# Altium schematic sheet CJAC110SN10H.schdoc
size 127 x 101 mm
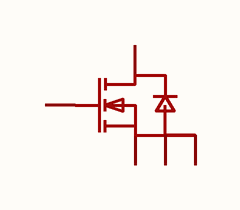
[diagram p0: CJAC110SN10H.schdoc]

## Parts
Q?  cjac110sn10h  [TDSON-8_L5.9-W5.2-P1.27-BL]  (value not drawn)

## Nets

Not connected (* = marked no-connect by the designer): Q? 1(S) 2(S) 3(S) 4(G) 5(D)

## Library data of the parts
Q? = cjac110sn10h: 数量:1个N沟道;漏源电压(Vdss):100V;连续漏极电流(Id):110A;导通电阻(RDS(on)):5.2mΩ@10V;耗散功率(Pd):130W;阈值电压(Vgs(th)):4V;; Manufacturer: CJ(江苏长电/长晶); AddInBom: yes; ModelId: ff3d8edf19694f3eb1c5df98919f3bc8; ModelTransform: 216.9287,242.5192,0,0,0,0,0,43.307,0; Number: 1个N沟道; Drain to Source Voltage: 100V; Current - Continuous Drain(Id): 110A; Pd - Power Dissipation: 130W; Gate Threshold Voltage (Vgs(th)): 4V; Gate Charge(Qg): 142nC@15V; Input Capacitance(Ciss): 6.134nF; Reverse Transfer Capacitance (Crss@Vds): 24pF; Type: N沟道; Output Capacitance(Coss): 1.376nF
